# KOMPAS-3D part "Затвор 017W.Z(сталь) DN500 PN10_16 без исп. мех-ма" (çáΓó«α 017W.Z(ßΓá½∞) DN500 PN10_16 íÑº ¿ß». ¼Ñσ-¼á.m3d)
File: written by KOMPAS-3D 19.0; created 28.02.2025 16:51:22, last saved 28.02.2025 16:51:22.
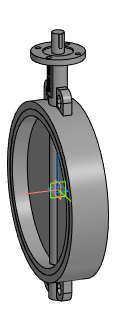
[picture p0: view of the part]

Document properties: Автор: Евгений; Полное имя файла: E:\Dendor Работа Сачек\3D для проекитирвщиков\1.5 Тип 017W.Z Сталь Затвор дисковый поворотный Межфланцевый\stp_Тип 017W.Z(сталь). Затвор без исполн. механизма\Затвор 017W.Z(сталь) DN500 PN10_16 без исп. мех-ма.m3d

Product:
- Part/product: Затвор 017W.Z(сталь) DN500 PN10_16 без исп. мех-ма

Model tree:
1. Операция без истории:1  (labels: Затвор 017W.Z(сталь) DN500 PN10_16 без исп. мех-ма)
